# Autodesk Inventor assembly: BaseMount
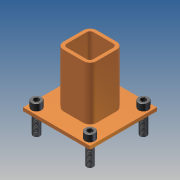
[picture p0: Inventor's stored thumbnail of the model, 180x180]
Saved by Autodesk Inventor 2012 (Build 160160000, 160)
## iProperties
Created: 2009-02
Part Number: BaseMount
Document SubType Name: Assembly
Designer: reaumed
Mass: 906.21 g
Surface Area: 948.667 cm^2
Volume: 270.093 cm^3
Density: 3.35518 g/cm^3
RuleStatus: InUse
Author: reaumed
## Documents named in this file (5)
- C:\CMU\Datasets\Session 5\iLogic\Sub Assemblies\BaseMount.iam
- C:\CMU\Datasets\Session 5\iLogic\Parts\Collar.ipt
- C:\CMU\Datasets\Session 5\iLogic\Parts\CollarBottomPlate.ipt
- C:\CMU\Datasets\Session 5\iLogic\Standard Components\SHCS\Screw-04.ipt
- C:\iLogicMain\Samples\Railing Basic\Standard Components\Screw.ipt
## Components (6 placed, 4 different names)
1. Collar_1 — Mate:1, Flush:1, Mate:2
2. CollarBottomPlate_1 — Mate:1, Flush:1, Mate:2, Mate:3, Mate:4
3. Screw — Mate:3, Mate:4
4. Screw-04:22
5. Screw-04:23
6. Screw-04:24
## Component patterns: Screw Pattern (4 elements)
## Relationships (5: Mate 4, Flush 1)
- Mate:1: Collar_1 ↔ CollarBottomPlate_1
- Flush:1: Collar_1 ↔ CollarBottomPlate_1
- Mate:2: Collar_1 ↔ CollarBottomPlate_1
- Mate:3: CollarBottomPlate_1 ↔ Screw
- Mate:4: CollarBottomPlate_1 ↔ Screw
